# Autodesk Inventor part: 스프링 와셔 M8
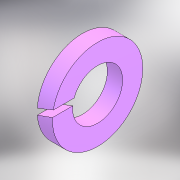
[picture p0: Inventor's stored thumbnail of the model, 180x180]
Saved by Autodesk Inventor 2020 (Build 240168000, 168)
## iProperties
Created: 2024-11
Part Number: 스프링 와셔 M8
Material: 강철, 연강
Description: 스프링 잠금 와셔
Document SubType Name: Modeling
Designer: 1강의실14
Density: 7.85 g/cm^3
Appearance: 기본값
Author: jhkim
Sending System: Autodesk Inventor 2025
Preprocessor: ST-DEVELOPER v20
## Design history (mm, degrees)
feature "Solid1"
node "솔리드1"
